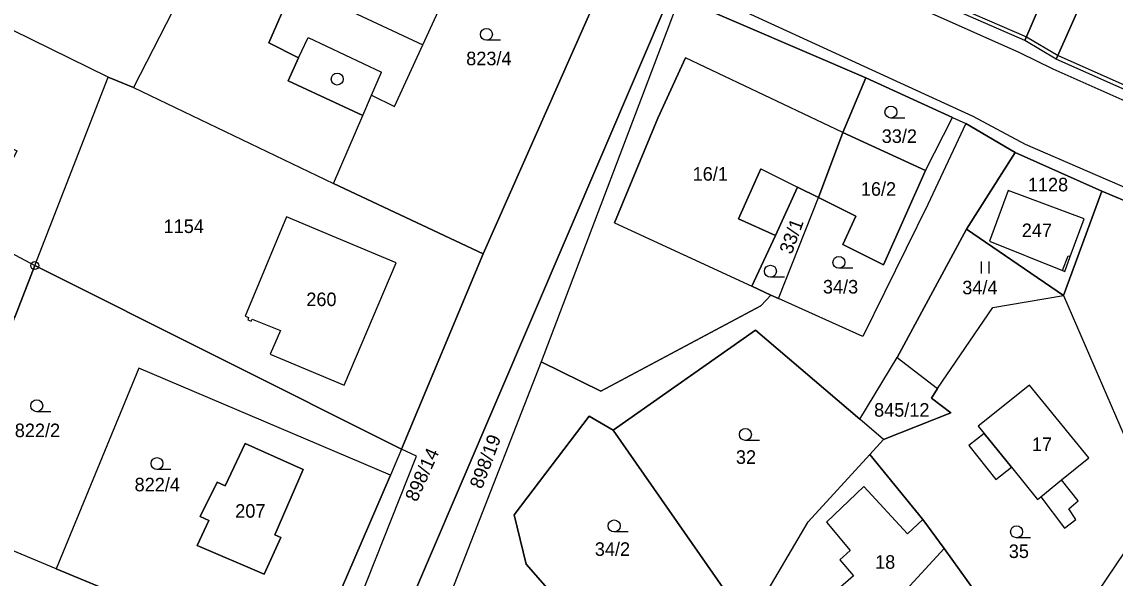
# Model space of a CAD drawing. Extents: x -654083 to -650132, y -1099819 to -1096699.
# Drawn here: x -652487.9 to -652350.7, y -1098002.5 to -1097932.6 of the extents above; entities that cross this region are included whole.
import ezdxf

# ---------------------------------------------------------------- set-up
doc = ezdxf.new("R2010")
doc.units = 0
for name, color, linetype in [('Geodetické body', 7, 'Continuous'), ('Hranice - vnitř_ kresba', 7, 'Continuous'), ('Obvody jako plochy', 7, 'Continuous'), ('Ostatní hranice', 7, 'Continuous'), ('Parcelní čísla', 7, 'Continuous'), ('Značky kultur', 7, 'Continuous')]:
    doc.layers.add(name, color=color, linetype=linetype)

msp = doc.modelspace()

# ---------------------------------------------------------------- linework, layer by layer
at = {"layer": 'Geodetické body'}
for radius in [0.5, 0.001]:
    msp.add_circle((-652486.26, -1097963.24), radius, dxfattribs=at)
at = {"layer": 'Hranice - vnitř_ kresba'}
for p, q in [((-652405.39, -1097927.55), (-652368.53, -1097944.47)), ((-652453.7, -1097927.96), (-652437.53, -1097935.54)), ((-652374.88, -1097931.06), (-652362.67, -1097936.49)), ((-652453.14, -1097937.16), (-652451.92, -1097934.62)), ((-652451.92, -1097934.62), (-652442.73, -1097938.94)), ((-652408.04, -1097944.75), (-652404.56, -1097937.14)), ((-652384.83, -1097946.54), (-652404.56, -1097937.14)), ((-652362.67, -1097936.49), (-652358.47, -1097938.54)), ((-652443.98, -1097941.83), (-652442.73, -1097938.94)), ((-652358.47, -1097938.54), (-652307.46, -1097961.3)), ((-652413.47, -1097957.86), (-652408.04, -1097944.75)), ((-652368.53, -1097944.47), (-652361.94, -1097947.99)), ((-652361.94, -1097947.99), (-652288.25, -1097980.07)), ((-652395.11, -1097951.11), (-652397.92, -1097957.36)), ((-652395.11, -1097951.11), (-652390.51, -1097953.39)), ((-652397.92, -1097957.36), (-652393.29, -1097959.44)), ((-652413.47, -1097957.86), (-652396.26, -1097965.83)), ((-652357.25, -1097963.87), (-652356.54, -1097962)), ((-652356.54, -1097962), (-652356.28, -1097962.09)), ((-652363.67, -1097988.54), (-652367.1, -1097984.31)), ((-652359.99, -1097992.27), (-652357.37, -1097990.11)), ((-652382.2, -1097990.97), (-652386.88, -1097995.45)), ((-652376.72, -1097996.92), (-652382.2, -1097990.97)), ((-652386.88, -1097995.45), (-652383.91, -1097998.98)), ((-652374.8, -1097995.09), (-652376.72, -1097996.92)), ((-652383.91, -1097998.98), (-652385.21, -1098000.16)), ((-652385.21, -1098000.16), (-652383.51, -1098002.19)), ((-652383.51, -1098002.19), (-652387.09, -1098005.32))]:
    msp.add_line(p, q, dxfattribs=at)
at = {"layer": 'Obvody jako plochy'}
for points in [[(-652839.76, -1097733.97), (-652826.6, -1097739.44), (-652822.57, -1097741.08), (-652707.93, -1097793.49), (-652704.24, -1097795.08), (-652617.25, -1097835.71), (-652588.75, -1097848.74), (-652581.26, -1097852.35), (-652575.63, -1097854.85), (-652550.17, -1097866.18), (-652501.51, -1097887.82), (-652496.71, -1097889.3), (-652483.12, -1097895.45), (-652482.5, -1097895.73), (-652456.7, -1097907.4), (-652446.55, -1097911.8), (-652439.64, -1097914.73), (-652414, -1097925.64), (-652406.37, -1097928.95), (-652405.33, -1097929.6), (-652381.94, -1097939.67)], [(-652259.95, -1097978.53), (-652289.58, -1097967.54), (-652304.17, -1097961.16), (-652306.89, -1097960.07), (-652358.06, -1097937.32), (-652361.99, -1097934.98), (-652373.04, -1097930.17), (-652374.25, -1097929.65), (-652375.24, -1097929.22), (-652386.86, -1097924.16), (-652403.6, -1097916.6), (-652409.91, -1097913.27), (-652436.78, -1097901.48), (-652463.96, -1097889.56), (-652483.6, -1097880.94), (-652534, -1097858.11), (-652537.59, -1097856.5), (-652554.49, -1097848.9), (-652581.83, -1097835.42), (-652676.84, -1097793.83), (-652695.77, -1097785.5), (-652811.07, -1097733.73)], [(-652346.41, -1097911.18), (-652358.06, -1097937.32), (-652361.99, -1097934.98), (-652350.86, -1097909.12)], [(-652381.94, -1097939.67), (-652371.06, -1097944.66), (-652369.4, -1097945.42), (-652363.18, -1097949.05), (-652352.33, -1097953.9), (-652321.55, -1097966.79)], [(-652418.63, -1098007.47), (-652424.56, -1098000.73), (-652426.1, -1097994.51), (-652416.66, -1097982.14), (-652413.64, -1097983.9), (-652395.81, -1097971.34), (-652382.71, -1097982.51), (-652378.02, -1097974.79), (-652369.3, -1097958.68), (-652363.18, -1097949.05), (-652369.4, -1097945.42), (-652374.18, -1097955.57), (-652382.31, -1097972.15), (-652392.92, -1097967.37), (-652393.87, -1097966.93), (-652395.13, -1097968.29), (-652415.19, -1097978.98), (-652422.68, -1097975.33), (-652437.49, -1098013.22)]]:
    msp.add_lwpolyline(points, dxfattribs=at)
for points in [[(-652456.7, -1097907.4), (-652473.86, -1097940.89), (-652477.05, -1097939.6), (-652493.87, -1097931.33), (-652489.03, -1097919.79), (-652487.21, -1097920.64), (-652483.15, -1097911.65), (-652477.44, -1097914.31), (-652474.61, -1097908.17), (-652485.4, -1097903.24), (-652482.5, -1097895.73)], [(-652570.9, -1097919.49), (-652557.26, -1097925.87), (-652555.49, -1097926.7), (-652556.9, -1097929.51), (-652553.63, -1097931.11), (-652554.87, -1097933.66), (-652526.83, -1097947.73), (-652524.35, -1097942.91), (-652486.26, -1097963.24), (-652488.77, -1097969.7), (-652512.28, -1097957.71), (-652524.21, -1097951.62), (-652548.1, -1097939.51), (-652608.36, -1097908.56), (-652604.34, -1097900.21), (-652570.36, -1097918.34)], [(-652517.85, -1097919.69), (-652522.91, -1097929.26), (-652529.14, -1097926), (-652523.95, -1097916.03), (-652525.47, -1097915.14), (-652551.8, -1097901.42), (-652552.63, -1097903.28), (-652547.71, -1097905.57), (-652552.96, -1097916.72), (-652488.51, -1097948.85), (-652492.9, -1097957.85), (-652524.09, -1097942.41), (-652524.35, -1097942.91), (-652486.26, -1097963.24), (-652477.05, -1097939.6), (-652493.87, -1097931.33), (-652500.29, -1097928.12), (-652516.82, -1097920.19)], [(-652456.89, -1097935.27), (-652453.7, -1097927.96), (-652449.19, -1097917.79), (-652446.55, -1097911.8), (-652456.7, -1097907.4), (-652473.86, -1097940.89), (-652448.75, -1097952.92), (-652445.08, -1097944.38), (-652454.46, -1097940.04), (-652453.14, -1097937.16)], [(-652355.23, -1097907.16), (-652350.86, -1097909.12), (-652361.99, -1097934.98), (-652373.04, -1097930.17), (-652370.58, -1097924.86), (-652369.95, -1097925.13), (-652369.36, -1097923.86), (-652363.59, -1097926.5), (-652360.31, -1097918.91)], [(-652437.53, -1097935.54), (-652432.88, -1097925.42), (-652442.33, -1097921.05), (-652439.64, -1097914.73), (-652446.55, -1097911.8), (-652449.19, -1097917.79), (-652453.7, -1097927.96), (-652456.89, -1097935.27), (-652453.14, -1097937.16), (-652454.46, -1097940.04), (-652445.08, -1097944.38), (-652443.98, -1097941.83), (-652441.08, -1097943.27)], [(-652306.95, -1097957.89), (-652303.66, -1097959.19), (-652304.17, -1097961.16), (-652306.89, -1097960.07), (-652358.06, -1097937.32), (-652346.41, -1097911.18), (-652296.09, -1097929.62), (-652301.21, -1097949.62), (-652303.07, -1097948.9)], [(-652443.98, -1097941.83), (-652441.08, -1097943.27), (-652437.53, -1097935.54), (-652432.88, -1097925.42), (-652442.33, -1097921.05), (-652439.64, -1097914.73), (-652414, -1097925.64), (-652429.99, -1097961.76), (-652448.75, -1097952.92), (-652445.08, -1097944.38)], [(-652406.37, -1097928.95), (-652441.31, -1098010.62), (-652447.9, -1098029.02), (-652446.63, -1098037.02), (-652449.67, -1098045.65), (-652448.23, -1098058.23), (-652448.88, -1098063.04), (-652447.64, -1098063.77), (-652446.77, -1098071.83), (-652437.07, -1098091.68), (-652437.83, -1098101.1), (-652440.05, -1098093.64), (-652454.71, -1098064.74), (-652452.31, -1098042.44), (-652453.12, -1098030.34), (-652446.61, -1098008.03), (-652438.33, -1097987.15), (-652440.24, -1097986.29), (-652429.99, -1097961.76), (-652414, -1097925.64)], [(-652405.33, -1097929.6), (-652422.68, -1097975.33), (-652437.49, -1098013.22), (-652439.91, -1098012.57), (-652445.26, -1098033.11), (-652446.63, -1098037.02), (-652447.9, -1098029.02), (-652441.31, -1098010.62), (-652406.37, -1097928.95)], [(-652384.83, -1097946.54), (-652381.94, -1097939.67), (-652405.33, -1097929.6), (-652422.68, -1097975.33), (-652415.19, -1097978.98), (-652395.13, -1097968.29), (-652393.87, -1097966.93), (-652396.26, -1097965.83), (-652393.29, -1097959.44), (-652390.51, -1097953.39), (-652387.9, -1097954.68)], [(-652413.47, -1097957.86), (-652396.26, -1097965.83), (-652393.29, -1097959.44), (-652397.92, -1097957.36), (-652395.11, -1097951.11), (-652390.51, -1097953.39), (-652387.9, -1097954.68), (-652384.83, -1097946.54), (-652404.56, -1097937.14), (-652408.04, -1097944.75)], [(-652473.86, -1097940.89), (-652448.75, -1097952.92), (-652429.99, -1097961.76), (-652440.24, -1097986.29), (-652486.26, -1097963.24), (-652477.05, -1097939.6)], [(-652374.46, -1097951.29), (-652371.06, -1097944.66), (-652381.94, -1097939.67), (-652384.83, -1097946.54)], [(-652374.46, -1097951.29), (-652371.06, -1097944.66), (-652369.4, -1097945.42), (-652374.18, -1097955.57), (-652382.31, -1097972.15), (-652392.92, -1097967.37), (-652387.9, -1097954.68), (-652383.18, -1097957.04), (-652384.85, -1097960.6), (-652379.74, -1097963.14)], [(-652374.46, -1097951.29), (-652384.83, -1097946.54), (-652387.9, -1097954.68), (-652383.18, -1097957.04), (-652384.85, -1097960.6), (-652379.74, -1097963.14)], [(-652387.9, -1097954.68), (-652384.83, -1097946.54), (-652374.46, -1097951.29), (-652379.74, -1097963.14), (-652384.85, -1097960.6), (-652383.18, -1097957.04)], [(-652363.18, -1097949.05), (-652369.3, -1097958.68), (-652357.13, -1097966.99), (-652352.33, -1097953.9)], [(-652393.87, -1097966.93), (-652392.92, -1097967.37), (-652387.9, -1097954.68), (-652390.51, -1097953.39), (-652393.29, -1097959.44), (-652396.26, -1097965.83)], [(-652354.52, -1097957.35), (-652364.08, -1097953.83), (-652366.41, -1097960.17), (-652357.25, -1097963.87), (-652356.98, -1097963.98), (-652356.28, -1097962.09)], [(-652354.52, -1097957.35), (-652364.08, -1097953.83), (-652366.41, -1097960.17), (-652357.25, -1097963.87), (-652356.98, -1097963.98), (-652356.28, -1097962.09)], [(-652366.41, -1097960.17), (-652357.25, -1097963.87), (-652356.54, -1097962), (-652356.28, -1097962.09), (-652354.52, -1097957.35), (-652364.08, -1097953.83)], [(-652342.75, -1097987.96), (-652341.4, -1097983.51), (-652339.55, -1097977.37), (-652330.83, -1097979.83), (-652330.17, -1097977.59), (-652324.69, -1097979.27), (-652325.26, -1097981.36), (-652321.28, -1097982.55), (-652321.55, -1097966.79), (-652352.33, -1097953.9), (-652357.13, -1097966.99), (-652348.97, -1097985.81)], [(-652459.41, -1097969.76), (-652459.52, -1097970.04), (-652459.07, -1097970.22), (-652458.96, -1097969.94), (-652455.41, -1097971.37), (-652456.71, -1097974.37), (-652447.41, -1097978.23), (-652440.91, -1097962.9), (-652450.19, -1097958.98), (-652454.65, -1097957.1), (-652459.83, -1097969.6)], [(-652459.41, -1097969.76), (-652459.52, -1097970.04), (-652459.07, -1097970.22), (-652458.96, -1097969.94), (-652455.41, -1097971.37), (-652456.71, -1097974.37), (-652447.41, -1097978.23), (-652440.91, -1097962.9), (-652450.19, -1097958.98), (-652454.65, -1097957.1), (-652459.83, -1097969.6)], [(-652459.41, -1097969.76), (-652459.52, -1097970.04), (-652459.07, -1097970.22), (-652458.96, -1097969.94), (-652455.41, -1097971.37), (-652456.71, -1097974.37), (-652447.41, -1097978.23), (-652440.91, -1097962.9), (-652450.19, -1097958.98), (-652454.65, -1097957.1), (-652459.83, -1097969.6)], [(-652372.95, -1097978.67), (-652366.01, -1097968.5), (-652357.13, -1097966.99), (-652369.3, -1097958.68), (-652378.02, -1097974.79)], [(-652441.6, -1097989.54), (-652473.21, -1097976.11), (-652483.55, -1098001.29), (-652498.57, -1097995.04), (-652488.77, -1097969.7), (-652486.26, -1097963.24), (-652440.24, -1097986.29)], [(-652342.75, -1097987.96), (-652340.9, -1097988.54), (-652347.14, -1097995.7), (-652349.54, -1097999.25), (-652356.14, -1098009.02), (-652368.28, -1098004.09), (-652372.1, -1097998.75), (-652374.8, -1097995.09), (-652381.45, -1097986.94), (-652379.72, -1097985.05), (-652371.29, -1097981.73), (-652373.72, -1097979.87), (-652372.95, -1097978.67), (-652366.01, -1097968.5), (-652357.13, -1097966.99), (-652348.97, -1097985.81)], [(-652389.17, -1097995.38), (-652381.45, -1097986.94), (-652379.72, -1097985.05), (-652382.71, -1097982.51), (-652395.81, -1097971.34), (-652413.64, -1097983.9), (-652396.73, -1098008.2)], [(-652378.02, -1097974.79), (-652372.95, -1097978.67), (-652373.72, -1097979.87), (-652371.29, -1097981.73), (-652379.72, -1097985.05), (-652382.71, -1097982.51)], [(-652452.29, -1098014.28), (-652441.6, -1097989.54), (-652473.21, -1097976.11), (-652483.55, -1098001.29)], [(-652355.29, -1097992.78), (-652357.37, -1097990.11), (-652353.95, -1097987.37), (-652361.4, -1097978.23), (-652367.86, -1097983.38), (-652367.1, -1097984.31), (-652369.02, -1097985.83), (-652365.64, -1097990.08), (-652363.67, -1097988.54), (-652360.39, -1097992.6), (-652359.99, -1097992.27), (-652357.01, -1097996.19), (-652355.58, -1097995.09), (-652356.48, -1097993.77)], [(-652357.01, -1097996.19), (-652355.58, -1097995.09), (-652356.48, -1097993.77), (-652355.29, -1097992.78), (-652357.37, -1097990.11), (-652353.95, -1097987.37), (-652361.4, -1097978.23), (-652367.86, -1097983.38), (-652367.1, -1097984.31), (-652369.02, -1097985.83), (-652365.64, -1097990.08), (-652363.67, -1097988.54), (-652360.39, -1097992.6), (-652359.99, -1097992.27)], [(-652357.37, -1097990.11), (-652353.95, -1097987.37), (-652361.4, -1097978.23), (-652367.86, -1097983.38), (-652367.1, -1097984.31), (-652363.67, -1097988.54), (-652360.39, -1097992.6), (-652359.99, -1097992.27)], [(-652413.64, -1097983.9), (-652416.66, -1097982.14), (-652426.1, -1097994.51), (-652424.56, -1098000.73), (-652418.63, -1098007.47), (-652401.98, -1098011.93), (-652396.73, -1098008.2)], [(-652463.37, -1097990.43), (-652462.34, -1097990.89), (-652459.83, -1097985.58), (-652452.55, -1097988.82), (-652456.1, -1097997.02), (-652455.37, -1097997.37), (-652457.45, -1098001.98), (-652465.85, -1097998.36), (-652464.39, -1097995.25), (-652465.48, -1097994.72)], [(-652457.45, -1098001.98), (-652455.37, -1097997.37), (-652456.1, -1097997.02), (-652452.55, -1097988.82), (-652459.83, -1097985.58), (-652462.34, -1097990.89), (-652463.37, -1097990.43), (-652465.48, -1097994.72), (-652464.39, -1097995.25), (-652465.85, -1097998.36)], [(-652464.39, -1097995.25), (-652465.85, -1097998.36), (-652457.45, -1098001.98), (-652455.37, -1097997.37), (-652456.1, -1097997.02), (-652452.55, -1097988.82), (-652459.83, -1097985.58), (-652462.34, -1097990.89), (-652463.37, -1097990.43), (-652465.48, -1097994.72)], [(-652453.12, -1098030.34), (-652446.61, -1098008.03), (-652438.33, -1097987.15), (-652440.24, -1097986.29), (-652441.6, -1097989.54), (-652452.29, -1098014.28), (-652455.34, -1098021.7), (-652458.39, -1098043.15)], [(-652374.8, -1097995.09), (-652372.1, -1097998.75), (-652384.95, -1098012.73), (-652388.7, -1098008.45), (-652396.73, -1098008.2), (-652389.17, -1097995.38), (-652381.45, -1097986.94)], [(-652374.8, -1097995.09), (-652376.72, -1097996.92), (-652382.2, -1097990.97), (-652386.88, -1097995.45), (-652383.91, -1097998.98), (-652385.21, -1098000.16), (-652383.51, -1098002.19), (-652387.09, -1098005.32), (-652384.95, -1098012.73), (-652372.1, -1097998.75)], [(-652472.7, -1098014.59), (-652455.34, -1098021.7), (-652452.29, -1098014.28), (-652483.55, -1098001.29), (-652498.57, -1097995.04), (-652501.65, -1098002.74)], [(-652377.36, -1098016.4), (-652379.26, -1098018.89), (-652384.95, -1098012.73), (-652372.1, -1097998.75), (-652368.28, -1098004.09)], [(-652332.87, -1098012.3), (-652349.54, -1097999.25), (-652356.14, -1098009.02), (-652352.91, -1098011.58), (-652353.89, -1098013.55), (-652343.87, -1098020.67)]]:
    msp.add_lwpolyline(points, close=True, dxfattribs=at)
for radius in [0.75, 0.001]:
    msp.add_circle((-652448.29, -1097939.82), radius, dxfattribs=at)
at = {"layer": 'Ostatní hranice'}
for p, q in [((-652386.6, -1097923.73), (-652361.76, -1097934.54)), ((-652361.76, -1097934.54), (-652357.82, -1097936.88)), ((-652357.82, -1097936.88), (-652303.89, -1097960.75))]:
    msp.add_line(p, q, dxfattribs=at)
at = {"layer": 'Značky kultur'}
for p, q in [((-652427.81, -1097934.96), (-652429.56, -1097934.96)), ((-652377.04, -1097944.72), (-652378.79, -1097944.72)), ((-652367.47, -1097962.71), (-652367.47, -1097964.21)), ((-652366.45, -1097964.21), (-652366.45, -1097962.71)), ((-652383.58, -1097963.58), (-652385.33, -1097963.58)), ((-652392.16, -1097964.69), (-652393.91, -1097964.69)), ((-652484.25, -1097981.58), (-652486, -1097981.58)), ((-652395.31, -1097985.18), (-652397.06, -1097985.18)), ((-652469.16, -1097988.83), (-652470.91, -1097988.83)), ((-652411.78, -1097996.66), (-652413.53, -1097996.66)), ((-652361.28, -1097997.4), (-652363.03, -1097997.4))]:
    msp.add_line(p, q, dxfattribs=at)
for centre in [(-652429.56, -1097934.21), (-652378.79, -1097943.97), (-652393.91, -1097963.94), (-652385.33, -1097962.83), (-652486, -1097980.83), (-652397.06, -1097984.43), (-652470.91, -1097988.08), (-652413.53, -1097995.91), (-652363.03, -1097996.65)]:
    msp.add_circle(centre, 0.75, dxfattribs=at)

# ---------------------------------------------------------------- texts
at = {"layer": 'Parcelní čísla'}
for s, p in [('823/4', (-652432.1, -1097938.09)), ('33/2', (-652379.95, -1097947.84)), ('16/1', (-652403.68, -1097952.58)), ('1128', (-652361.61, -1097953.92)), ('16/2', (-652382.57, -1097954.47)), ('1154', (-652470.08, -1097959.15)), ('247', (-652362.37, -1097959.66)), ('34/3', (-652387.33, -1097966.74)), ('34/4', (-652369.84, -1097966.84)), ('260', (-652452.17, -1097968.32)), ('845/12', (-652380.91, -1097982.2)), ('822/2', (-652488.76, -1097984.77)), ('17', (-652361.1, -1097986.51)), ('32', (-652398.25, -1097988.12)), ('822/4', (-652473.72, -1097991.57)), ('207', (-652461.09, -1097994.88)), ('34/2', (-652415.96, -1097999.67)), ('35', (-652364, -1097999.94)), ('18', (-652380.78, -1098001.29))]:
    msp.add_text(s, height=1.7, dxfattribs=at).set_placement(p)
for s, rotation, p in [('33/1', 69.633, (-652391.26, -1097961.92)), ('898/19', 69.48, (-652430.13, -1097991.37)), ('898/14', 65.79, (-652438.3, -1097992.99))]:
    msp.add_text(s, height=1.7, rotation=rotation, dxfattribs=at).set_placement(p)

doc.saveas('drawing.dxf')
